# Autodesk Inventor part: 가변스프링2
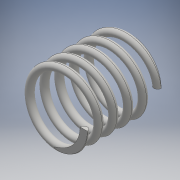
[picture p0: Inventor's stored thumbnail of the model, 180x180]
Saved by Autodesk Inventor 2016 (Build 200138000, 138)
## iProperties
Created: 2019-11
Part Number: 가변스프링2
Material: 일반
Document SubType Name: Modeling
Designer: user
Density: 1 g/cm^3
Appearance: 기본값
Mass: 0.821961 g
Surface Area: 16.7185 cm^2
Volume: 0.821961 cm^3
Author: user
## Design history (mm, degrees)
sketch "스케치1"
  geometry: L1 (0, 0)-(8.5, 0); L2 (8.5, 0)-(8.5, 20.5); L3 (8.5, 20.5)-(0, 20.5); L4 (0, 20.5)-(0, 0); C1 r 1 at (8.5, 0)
  constraints: 8 end point, 2 parallel, 1 centre point, 1 coincident, 1 horizontal, 1 perpendicular
  dimensions: "d1" = 17 diameter of L2 L4; "d2" = 20.5 distance between parallel lines of L1 L3 (derived); "d3" = 2 diameter of C1
feature "코일1" sketch "스케치1" pitch "d4" = 10; turns "d6" = 5; dims "d5" = 20.5 (= d2), "d7" = 0, angle "d8" = 90 deg, angle "d9" = 90 deg, "d10" = 0, "d11" = 0
sketch "스케치2"
  geometry: L1 (0, 13.879)-(20.5, 13.879); L2 (20.5, 13.879)-(20.5, -13.879); L3 (20.5, -13.879)-(0, -13.879); L4 (0, -13.879)-(0, 13.879); 2 further points
  constraints: 8 end point, 2 parallel, 1 coincident, 1 horizontal, 1 midpoint, 1 perpendicular
  dimensions: "d12" = 20.5 distance between parallel lines of L4 L2 (= d2); "d13" = 27.7574 distance between parallel lines of L1 L3
extrude "돌출1" sketch "스케치2" stored distance "d14" = 50; taper "d15" = 0 deg
node "솔리드1"
